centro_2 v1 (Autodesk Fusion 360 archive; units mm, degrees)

design "centro_2" references "a_medioLateralIZQ", "a_centro_atras", "a_centro_adelante_final"
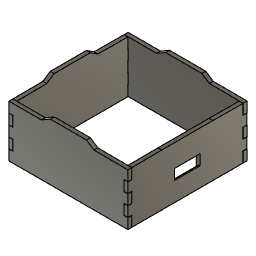
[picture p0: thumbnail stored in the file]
component_insert "Component Insert1"
component_insert "Component Insert2"
component_insert "Component Insert4"
component_insert "Component Insert5"

design "a_centro_atras"
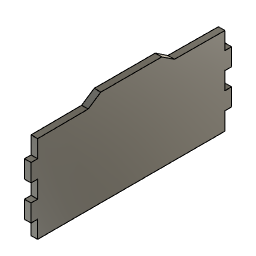
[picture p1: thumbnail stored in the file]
sketch "Sketch1" plane through (0, 0, 0) normal (1, 0, 0) x axis (0, 1, 0)
  line L1 (300, 220) -> (160, 220)
  line L2 (15, 0) -> (444.8, 0)
  line L3 (300, 220) -> (230, 220)
  line L4 (160, 220) -> (230, 220)
  line L5 (328.7889, 200.8074) -> (300, 220)
  line L6 (131.2111, 200.8074) -> (160, 220)
  line L7 (15.2, 160.15) -> (15.2, 200)
  line L8 (0, 160.15) -> (15.2, 160.15)
  line L9 (0, 119.6381) -> (15.2, 119.6381)
  line L10 (15.2, 79.7881) -> (0, 79.7881)
  line L11 (15.2, 119.6381) -> (15.2, 79.7881)
  line L12 (444.8, 160.15) -> (460, 160.15)
  line L13 (460, 120.3) -> (444.8, 120.3)
  line L14 (460, 160.15) -> (460, 120.3)
  line L15 (444.8, 160.15) -> (444.8, 200)
  line L16 (460, 160.15) -> (444.8, 160.15)
  line L17 (444.8, 120.3) -> (460, 120.3)
  line L18 (444.8, 80.45) -> (444.8, 120.3)
  line L19 (460, 80.45) -> (444.8, 80.45)
  line L20 (444.8, 200) -> (328.7889, 200.8074)
  line L21 (460, 120.3) -> (460, 160.15)
  line L22 (460, 40.6) -> (460, 80.45)
  line L23 (15.2, 160.15) -> (15.2, 200)
  line L24 (0, 160.15) -> (15.2, 160.15)
  line L25 (0, 79.7881) -> (0, 39.894)
  line L26 (0, 160.15) -> (0, 119.6381)
  line L27 (15, 39.894) -> (0, 39.894)
  line L28 (15, 0) -> (15, 39.894)
  line L29 (0, 0) -> (15, 0)
  line L30 (444.8, 80.45) -> (460, 80.45)
  line L31 (460, 40.6) -> (444.8, 40.6)
  line L32 (460, 80.45) -> (460, 40.6)
  line L33 (460, 40.6) -> (444.8, 40.6)
  line L34 (444.8, 40.6) -> (444.8, 0)
  line L35 (131.2111, 200.8074) -> (15.2, 200)
  point P2 (230, 220)
  point P3 (300, 220)
  point P4 (160, 220)
  point P5 (328.7889, 200.8074)
  point P6 (131.2111, 200.8074)
  point P10 (15.2, 119.6381)
  point P13 (15.2, 79.7881)
  point P14 (460, 160.15)
  point P15 (444.8, 160.15)
  point P17 (460, 120.3)
  point P22 (460, 80.45)
  point P29 (444.8, 80.45)
  point P31 (460, 40.6)
  horizontal L1
  horizontal L2
  vertical L25
  vertical L7
  horizontal L8
  horizontal L9
  horizontal L10
  vertical L11
  horizontal L12
  horizontal L13
  vertical L14
  vertical L15
  horizontal L16
  horizontal L17
  vertical L18
  horizontal L19
  coincident L1 P2
  collinear L21 L22
  vertical L23
  horizontal L24
  collinear L25 L26
  horizontal L27
  vertical L28
  horizontal L29
  horizontal L30
  horizontal L31
  vertical L32
  horizontal L33
  vertical L34
  dimension "d2" distance P2 P3 = 70
  dimension "d3" distance P2 P4 = 70
  dimension "d5" distance P3 P5 = 34.6
  dimension "d6" distance P4 P6 = 34.6
  dimension "d10" distance P10 P13 = 39.85
  dimension "d11" distance P14 P15 = 15.2
  dimension "d14" distance P17 P22 = 39.85
  dimension "d15" distance P22 P29 = 15.2
  dimension "d16" distance P22 P31 = 39.85
extrude "Extrude1" new body sketch "Sketch1" profile of L1 L22 L2 L26 L3 L4 L5 L6 L7 L8 L9 L10 L11 L12 L13 L14 L15 L16 L17 L18 L19 L20 L23 L24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 along normal blind 15

design "a_medioLateralIZQ"
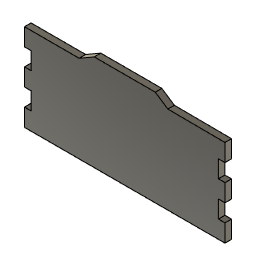
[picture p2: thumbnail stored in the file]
sketch "Sketch1" plane through (0, 0, 0) normal (0, 1, 0) x axis (1, 0, 0)
  line L1 (460, 0) -> (0, 0)
  line L2 (0, -200) -> (125.4, -200)
  line L3 (160, -220) -> (125.4, -200)
  line L4 (328.7889, -200.8074) -> (300, -220)
  line L5 (460, -160) -> (460, -200)
  line L6 (444.8, -160) -> (460, -160)
  line L7 (444.8, -120.15) -> (444.8, -160)
  line L8 (460, -120.15) -> (444.8, -120.15)
  line L9 (444.8, -80.15) -> (460, -80.15)
  line L10 (444.8, -40.3) -> (444.8, -80.15)
  line L11 (460, -40.3) -> (444.8, -40.3)
  line L12 (15.2, -160) -> (0, -160)
  line L13 (15.2, -120.15) -> (15.2, -160)
  line L14 (0, -120.15) -> (15.2, -120.15)
  line L15 (15.2, -80.15) -> (0, -80.15)
  line L16 (15.2, -40.3) -> (15.2, -80.15)
  line L17 (0, -40.3) -> (15.2, -40.3)
  line L18 (460, -200) -> (328.7889, -200.8074)
  line L19 (460, -200) -> (460, -160)
  line L20 (460, -40.3) -> (460, 0)
  line L21 (460, -120.15) -> (460, -80.15)
  line L22 (0, 0) -> (0, -40.3)
  line L23 (0, -160) -> (0, -200)
  line L24 (0, -80.15) -> (0, -120.15)
  line L25 (300, -220) -> (160, -220)
  point P1 (0, 0)
  point P2 (0, 0)
  point P14 (460, -80.15)
  point P3 (460, 0)
  point P10 (460, -160)
  point P13 (460, -120.15)
  point P15 (444.8, -80.15)
  point P17 (460, -40.3)
  point P18 (0, -160)
  point P19 (15.2, -160)
  point P21 (0, -120.15)
  point P22 (0, -80.15)
  point P23 (15.2, -80.15)
  point P25 (0, -40.3)
  horizontal L1
  vertical L20
  vertical L23
  coincident P1 P2
  perpendicular L2 L23
  horizontal L6
  vertical L7
  horizontal L8
  horizontal L9
  vertical L10
  horizontal L11
  coincident P14 L20
  horizontal L12
  vertical L13
  horizontal L14
  horizontal L15
  vertical L16
  horizontal L17
  collinear L19 L20
  collinear L20 L21
  collinear L22 L23
  collinear L23 L24
  horizontal L25
  dimension "d1" distance P2 P3 = 460
  dimension "d10" distance P10 P13 = 39.85
  dimension "d11" distance P14 P15 = 15.2
  dimension "d12" distance P14 P17 = 39.85
  dimension "d13" distance P13 P14 = 40
  dimension "d14" distance P18 P19 = 15.2
  dimension "d15" distance P18 P21 = 39.85
  dimension "d16" distance P22 P23 = 15.2
  dimension "d17" distance P22 P25 = 39.85
extrude "Extrude1" new body sketch "Sketch1" profile of L1 L21 L24 L2 L3 L4 L5 L6 L7 L8 L9 L10 L11 L12 L13 L14 L15 L16 L17 L18 L25 along normal blind 15

design "a_centro_adelante_final"
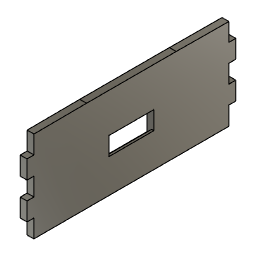
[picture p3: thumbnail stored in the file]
sketch "Sketch1" plane through (0, 0, 0) normal (1, 0, 0) x axis (0, 1, 0)
  line L1 (15, 0) -> (444.8, 0)
  line L2 (15.2, 160.15) -> (15.2, 200)
  line L3 (0, 160.15) -> (15.2, 160.15)
  line L4 (0, 119.6381) -> (15.2, 119.6381)
  line L5 (15.2, 79.7881) -> (0, 79.7881)
  line L6 (15.2, 119.6381) -> (15.2, 79.7881)
  line L7 (444.8, 160.15) -> (460, 160.15)
  line L8 (460, 120.3) -> (444.8, 120.3)
  line L9 (460, 160.15) -> (460, 120.3)
  line L10 (444.8, 160.15) -> (444.8, 200)
  line L11 (460, 160.15) -> (444.8, 160.15)
  line L12 (444.8, 120.3) -> (460, 120.3)
  line L13 (444.8, 80.45) -> (444.8, 120.3)
  line L14 (460, 80.45) -> (444.8, 80.45)
  line L15 (444.8, 200) -> (328.7889, 200.8074)
  line L16 (460, 120.3) -> (460, 160.15)
  line L17 (460, 40.6) -> (460, 80.45)
  line L18 (15.2, 160.15) -> (15.2, 200)
  line L19 (0, 160.15) -> (15.2, 160.15)
  line L20 (0, 79.7881) -> (0, 39.894)
  line L21 (0, 160.15) -> (0, 119.6381)
  line L22 (15, 39.894) -> (0, 39.894)
  line L23 (15, 0) -> (15, 39.894)
  line L24 (0, 0) -> (15, 0)
  line L25 (444.8, 80.45) -> (460, 80.45)
  line L26 (460, 40.6) -> (444.8, 40.6)
  line L27 (460, 80.45) -> (460, 40.6)
  line L28 (460, 40.6) -> (444.8, 40.6)
  line L29 (444.8, 40.6) -> (444.8, 0)
  line L30 (131.2111, 200.8074) -> (15.2, 200)
  line L31 (279.5, 64.4277) -> (180.5, 124.4277)
  line L32 (180.5, 64.4277) -> (279.5, 124.4277)
  line L33 (279.5, 114.5277) -> (180.5, 114.5277)
  line L34 (279.5, 74.3277) -> (279.5, 114.5277)
  line L35 (180.5, 74.3277) -> (279.5, 74.3277)
  line L36 (180.5, 114.5277) -> (180.5, 74.3277)
  line L37 (279.5, 74.3277) -> (180.5, 114.5277)
  line L38 (180.5, 74.3277) -> (279.5, 114.5277)
  line L39 (131.2111, 200.8074) -> (328.7889, 200.8074)
  point P35 (230, 94.4277)
  point P40 (230, 94.4277)
  point P7 (15.2, 119.6381)
  point P10 (15.2, 79.7881)
  point P11 (460, 160.15)
  point P12 (444.8, 160.15)
  point P14 (460, 120.3)
  point P19 (460, 80.45)
  point P26 (444.8, 80.45)
  point P28 (460, 40.6)
  point P37 (279.5, 114.5277)
  point P38 (279.5, 74.3277)
  horizontal L1
  vertical L20
  vertical L2
  horizontal L3
  horizontal L4
  horizontal L5
  vertical L6
  horizontal L7
  horizontal L8
  vertical L9
  vertical L10
  horizontal L11
  horizontal L12
  vertical L13
  horizontal L14
  collinear L16 L17
  vertical L18
  horizontal L19
  collinear L20 L21
  horizontal L22
  vertical L23
  horizontal L24
  horizontal L25
  horizontal L26
  vertical L27
  horizontal L28
  vertical L29
  coincident L31 P35
  coincident L32 P35
  horizontal L33
  perpendicular L33 L34
  parallel L33 L35
  parallel L34 L36
  coincident L37 P40
  coincident L38 P40
  coincident P35 P40
  horizontal L39
  dimension "d10" distance P7 P10 = 39.85
  dimension "d11" distance P11 P12 = 15.2
  dimension "d14" distance P14 P19 = 39.85
  dimension "d15" distance P19 P26 = 15.2
  dimension "d16" distance P19 P28 = 39.85
  dimension "d22" distance P37 P38 = 40.2
extrude "Extrude1" new body sketch "Sketch1" profile of L17 L1 L21 L2 L3 L4 L5 L6 L7 L8 L9 L10 L11 L12 L13 L14 L15 L18 L19 L22 L23 L25 L26 L27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 along normal blind 15
extrude "Extrude2" cut sketch "Sketch1" profile of L33 L34 L35 L36 along normal blind 20
sketch "Sketch2" plane through (0, 0, 0) normal (1, 0, 0) x axis (0, 1, 0)
  line L1 (180.5, 125) -> (279.5, 125)
  line L2 (279.5, 65) -> (180.5, 65)
  line L3 (279.5, 125) -> (279.5, 65)
  line L4 (180.5, 65) -> (279.5, 125)
  line L5 (279.5, 65) -> (180.5, 125)
  line L6 (180.5, 65) -> (180.5, 125)
  point P6 (230, 95)
  point P4 (180.5, 65)
  point P5 (279.5, 65)
  point P3 (180.5, 125)
  horizontal L1
  parallel L1 L2
  coincident L4 P6
  coincident L5 P6
  perpendicular L1 L6
  dimension "d25" distance P4 P5 = 99
  dimension "d26" distance P3 P4 = 60
extrude "Extrude3" cut sketch "Sketch2" profile of L1 L2 L3 L6 along normal blind 10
